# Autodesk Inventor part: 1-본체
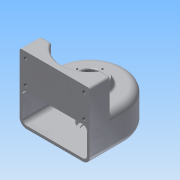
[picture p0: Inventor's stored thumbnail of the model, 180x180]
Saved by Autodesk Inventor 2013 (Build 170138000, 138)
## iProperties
Created: 2015-02
Part Number: 1-본체
Material: 알루미늄 6061
Document SubType Name: Modeling
Designer: Administrator
Density: 2.71 g/cm^3
Mass: 575.282 g
Surface Area: 707.302 cm^2
Volume: 212.281 cm^3
Author: Administrator
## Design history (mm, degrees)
sketch "스케치1"
  geometry: L1 (50, -25)-(-50, -25); L2 (-50, -25)-(-50, 25); L3 (-50, 25)-(50, 25); L4 (50, 25)-(50, -25); L5 (50, -25)-(-50, 25); L6 (-50, -25)-(50, 25); C1 r 50 at (0, 25); 2 further points
  constraints: 12 end point, 3 midpoint, 2 parallel, 1 centre point, 1 horizontal, 1 perpendicular, 1 vertical alignment
  dimensions: "d0" = 50 distance of L1.end L2.end; "d2" = 100 distance of L1.start L1.end; "d3" = 50 radius of C1; "d4" = 50 distance from line of L1 C1.centre
extrude "돌출1" new body sketch "스케치1" distance "d5" = 50; taper "d6" = 0 deg
sketch "스케치2"
  geometry: L1 (-50, 25)-(-50, -25) reference; L2 (-50, -25)-(50, -25) reference; L3 (50, -25)-(50, 25) reference; L4 (-50, 5)-(50, 5); 1 further point
  constraints: 2 end point, 2 point on line, 1 perpendicular
  dimensions: "d7" = 30 distance between parallel lines of L2 L4
extrude "돌출2" join sketch "스케치2" distance "d8" = 45; taper "d9" = 0 deg
node "작업 평면1"
sketch "스케치3"
  geometry: L1 (-50, -25)-(50, -25) reference; C1 r 40 at (0, 25); 1 further point
  constraints: 1 centre point, 1 vertical alignment
  dimensions: "d11" = 50 distance from line of C1.centre L1; "d12" = 40 radius of C1
extrude "돌출3" cut sketch "스케치3" distance "d13" = 50; taper "d14" = 0 deg
sketch "스케치4"
  geometry: C1 r 25 at (0, 25); A1 r 40 centre (0, 25) between (-34.641, 5) and (34.641, 5) reference; 1 further point
  constraints: 1 centre point, 1 coincident
  dimensions: "d15" = 50 diameter of C1
extrude "돌출4" join sketch "스케치4" distance "d17" = 10; taper "d18" = -20 deg
sketch "스케치5"
  geometry: C1 r 20 at (0, 25); A1 r 50 centre (0, 25) between (50, 25) and (-50, 25) reference; 1 further point
  constraints: 1 centre point, 1 coincident
  dimensions: "d19" = 40 diameter of C1
extrude "돌출5" join sketch "스케치5" distance "d21" = 9; taper "d22" = 0 deg
node "작업 평면2"
sketch "스케치6"
  geometry: L1 (50, 25)-(50, -25) reference; L2 (-50, -25)-(-50, 25) reference; L3 (50, -25)-(-50, -25) reference; L4 (46, 25)-(46, -21); L5 (-46, -21)-(-46, 25); L6 (46, -21)-(46, -25); L7 (-46, -21)-(-46, -25); A1 r 50 centre (0, 25) between (50, 25) and (-50, 25) reference; A2 r 46 centre (0, 25) between (46, 25) and (-46, 25); 1 further point
  constraints: 8 end point, 2 perpendicular, 2 point on circle, 2 point on line, 1 centre point, 1 tangent, 1 other
  dimensions: "d25" = 46 radius of A2; "d26" = 90 deg angle of L5 L3; "d27" = 4 distance from line of L4.end L3; "d28" = 4 distance from line of L5.start L3
extrude "돌출6" cut sketch "스케치6" stored distance "d29" = 42; taper "d30" = 0 deg
sketch "스케치7"
  geometry: L1 (100, 0)-(0, 0) reference; L2 (0, 95)-(100, 95) reference; L3 (91.75, 86)-(8.25, 86); L4 (8.25, 86)-(8.25, 53); L5 (8.25, 53)-(91.75, 53); L6 (91.75, 53)-(91.75, 86); 7 further points
  constraints: 8 end point, 4 coincident, 2 midpoint, 2 parallel, 1 horizontal, 1 perpendicular, 1 vertical alignment
  dimensions: "d31" = 83.5 distance of L3.start L3.end; "d33" = 33 distance of L5.end L3.start; "d34" = 9 distance between parallel lines of L3 L2
hole "구멍1" sketch "스케치7" at (91.75, 86), (8.25, 86), (8.25, 53), (91.75, 53) diameter "d35" = 5.134; stored, may be unused: countersink angle "d39" = 90 deg, drill point angle "d41" = 118 deg; dims "d36" = 10, "d37" = 4, "d38" = 2, "d40" = 13
hole "구멍2" diameter "d44" = 20; stored, may be unused: countersink angle "d48" = 90 deg, drill point angle "d50" = 0 deg; dims "d42" = 10, "d43" = 10, "d45" = 20, "d46" = 28, "d47" = 10, "d49" = 14
sketch "스케치8"
  geometry: A1 r 46 centre (0, 25) between (46, 25) and (-46, 25) reference; 1 further point
hole "구멍3" sketch "스케치8" at (0, 25) diameter "d51" = 20; stored, may be unused: countersink angle "d55" = 90 deg, drill point angle "d57" = 0 deg; dims "d52" = 6, "d53" = 28, "d54" = 8, "d56" = 10
sketch "스케치9"
  geometry: C1 r 14 at (0, 0) reference; C2 r 21.36 at (0, 0) reference; A1 r 18 centre (0, 0) between (0, 18) and (0, -18); 3 further points
  constraints: 4 point on circle, 2 horizontal alignment, 2 vertical alignment, 1 centre point, 1 coincident
  dimensions: "d58" = 36 diameter of A1
node "작업 평면3"
sketch "스케치10"
  geometry: L1 (-100, 0)-(0, 0) reference; 3 further points
  constraints: 1 midpoint, 1 vertical alignment, 1 other
  dimensions: "d61" = 25 distance of point (-50, 0) point (-50, 25)
feature "엠보싱1" sketch "스케치10" dims "d0" = 50, "d2" = 100, "d3" = 50, "d4" = 50, "d11" = 50, "d12" = 40, "d62" = 0.5, "d63" = 0
fillet "모깎기1" dims "d64" = 10
fillet "모깎기2" dims "d65" = 6
fillet "모깎기3" dims "d66" = 0.3
chamfer "모따기1" distance "d67" = 1; stored, may be unused: second distance "d68" = 2, angle "d69" = 45 deg
fillet "모깎기4" dims "d70" = 3
fillet "모깎기5" dims "d71" = 3
fillet "모깎기6" dims "d72" = 3
fillet "모깎기7" dims "d73" = 3
fillet "모깎기8" dims "d74" = 3
sketch "스케치11"
  geometry: C1 r 21.36 at (0, 0) reference; C2 r 15 at (0, 0) reference; A1 r 18 centre (0, 0) between (0, 18) and (-18, 0); 3 further points
  constraints: 4 point on circle, 2 horizontal alignment, 2 vertical alignment, 1 centre point, 1 coincident
  dimensions: "d75" = 36 diameter of A1
hole "구멍4" sketch "스케치11" at (0, 18), (-18, 0), (0, -18), (18, 0) diameter "d77" = 2.459; stored, may be unused: countersink angle "d81" = 90 deg, drill point angle "d83" = 118 deg; dims "d78" = 6, "d79" = 4, "d80" = 2, "d82" = 9
node "솔리드1"
other parameters: "d10" = 0, "d23" = 25
